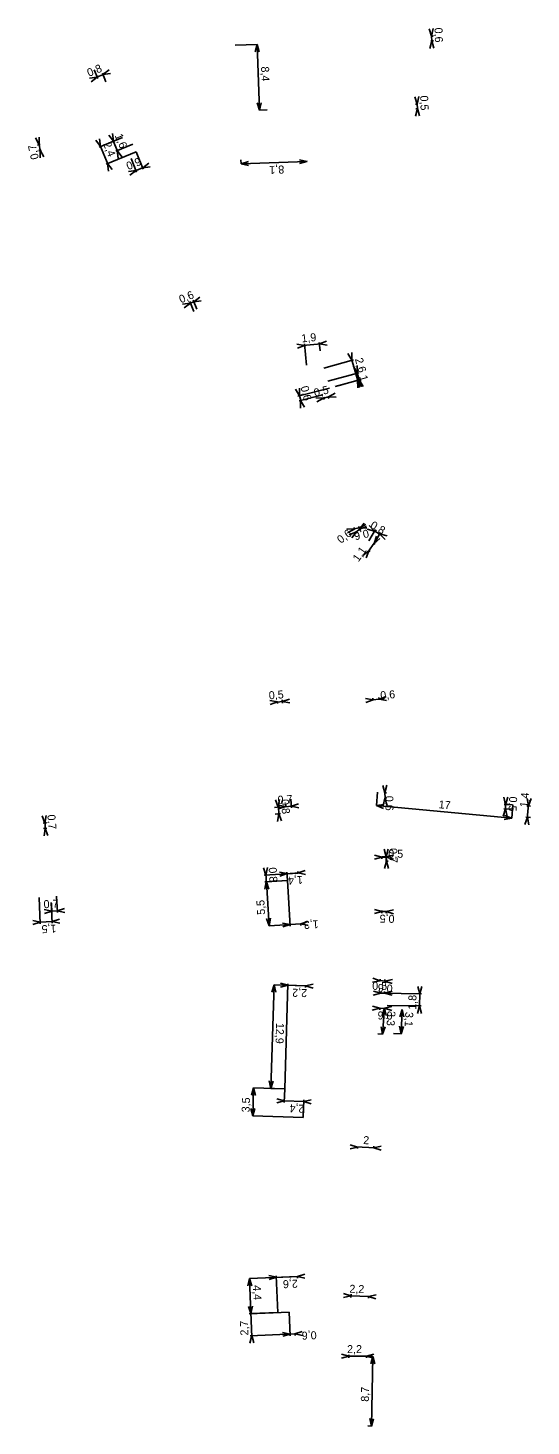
# Model space of a CAD drawing. Extents: x -732085 to -731961, y -1048713 to -1047966.
# Drawn here: x -732023.7 to -731960.7, y -1048713.1 to -1048538.4 of the extents above; entities that cross this region are included whole.
import ezdxf

# ---------------------------------------------------------------- set-up
doc = ezdxf.new("R2010")
doc.units = 0
doc.layers.add('Kota_NN', color=7, linetype='Continuous')
doc.layers.add('Kota_VN', color=7, linetype='Continuous')

msp = doc.modelspace()

# ---------------------------------------------------------------- linework, layer by layer
at = {"layer": 'Kota_NN'}
for p, q in [((-731973.19, -1048539.41), (-731973.47, -1048538.49)), ((-731973.19, -1048539.41), (-731972.97, -1048538.47)), ((-731997.73, -1048540.53), (-731995.01, -1048540.43)), ((-731995.01, -1048540.43), (-731995.23, -1048541.37)), ((-731995.01, -1048540.43), (-731994.7, -1048548.67)), ((-731995.01, -1048540.43), (-731994.73, -1048541.35)), ((-731973.16, -1048539.99), (-731973.38, -1048540.93)), ((-731973.27, -1048540), (-731972.96, -1048539.99)), ((-731973.26, -1048539.41), (-731972.98, -1048539.4)), ((-731973.19, -1048539.21), (-731973.16, -1048540.19)), ((-731973.16, -1048539.99), (-731972.88, -1048540.91)), ((-732015.38, -1048543.6), (-732014.93, -1048544.7)), ((-732015.19, -1048544.59), (-732014.09, -1048544.14)), ((-732013.9, -1048545.12), (-732014.35, -1048544.03)), ((-732014.28, -1048544.21), (-732013.51, -1048543.63)), ((-732014.28, -1048544.21), (-732013.33, -1048544.09)), ((-732015.01, -1048544.52), (-732015.96, -1048544.64)), ((-732015.01, -1048544.52), (-732015.77, -1048545.1)), ((-731974.98, -1048547.9), (-731975.26, -1048546.98)), ((-731974.98, -1048547.9), (-731974.76, -1048546.96)), ((-731974.98, -1048547.7), (-731974.95, -1048548.67)), ((-731994.7, -1048548.67), (-731994.99, -1048547.75)), ((-731994.7, -1048548.67), (-731994.49, -1048547.73)), ((-731993.73, -1048548.63), (-731994.7, -1048548.67)), ((-731974.95, -1048547.89), (-731975.18, -1048547.9)), ((-731974.96, -1048548.46), (-731975.18, -1048549.4)), ((-731974.95, -1048548.46), (-731975.16, -1048548.47)), ((-731974.96, -1048548.46), (-731974.68, -1048549.38)), ((-732022.27, -1048552.97), (-732022.72, -1048552.13)), ((-732022.14, -1048552.94), (-732022.46, -1048553.02)), ((-732022.07, -1048553.84), (-732022.31, -1048552.78)), ((-732022.27, -1048552.97), (-732022.24, -1048552.01)), ((-732014.58, -1048553.18), (-732015.16, -1048552.42)), ((-732011.84, -1048552.06), (-732014.76, -1048553.26)), ((-732014.58, -1048553.18), (-732014.7, -1048552.23)), ((-732012.97, -1048552.52), (-732013.55, -1048551.76)), ((-732011.84, -1048552.06), (-732013.16, -1048552.6)), ((-732012.97, -1048552.52), (-732013.09, -1048551.57)), ((-732013.05, -1048552.34), (-732012.41, -1048553.89)), ((-732010.53, -1048552.9), (-732012.67, -1048553.78)), ((-732021.99, -1048553.61), (-732022.31, -1048553.69)), ((-732022.11, -1048553.64), (-732022.14, -1048554.6)), ((-732022.11, -1048553.64), (-732021.66, -1048554.49)), ((-732014.65, -1048553), (-732013.63, -1048555.49)), ((-732010.14, -1048553.84), (-732013.89, -1048555.38)), ((-732012.48, -1048553.71), (-732011.9, -1048554.47)), ((-732012.48, -1048553.71), (-732012.36, -1048554.66)), ((-732010.14, -1048553.84), (-732009.24, -1048556.04)), ((-732013.71, -1048555.3), (-732013.13, -1048556.07)), ((-732013.71, -1048555.3), (-732013.59, -1048556.26)), ((-732010.14, -1048556.19), (-732011.1, -1048556.32)), ((-732010.14, -1048556.19), (-732010.91, -1048556.78)), ((-732010.75, -1048554.71), (-732010.07, -1048556.38)), ((-732010.33, -1048556.27), (-732009.13, -1048555.78)), ((-732009.31, -1048555.85), (-732008.55, -1048555.27)), ((-732009.31, -1048555.85), (-732008.36, -1048555.73)), ((-731997.02, -1048554.85), (-731997, -1048555.37)), ((-731988.77, -1048555.05), (-731997, -1048555.37)), ((-731997, -1048555.37), (-731996.08, -1048555.08)), ((-731997, -1048555.37), (-731996.06, -1048555.58)), ((-731988.77, -1048555.05), (-731989.71, -1048554.84)), ((-731988.77, -1048555.05), (-731989.69, -1048555.33)), ((-731988.77, -1048555), (-731988.77, -1048555.05)), ((-732002.93, -1048572.58), (-732002.17, -1048572)), ((-732003.35, -1048572.75), (-732004.31, -1048572.87)), ((-732003.35, -1048572.75), (-732004.12, -1048573.33)), ((-732003.54, -1048572.83), (-732002.75, -1048572.5)), ((-732002.93, -1048573.79), (-732003.43, -1048572.57)), ((-732002.55, -1048573.51), (-732003.01, -1048572.39)), ((-732002.93, -1048572.58), (-732001.98, -1048572.46)), ((-731989.07, -1048578.05), (-731990.02, -1048577.89)), ((-731989.07, -1048578.05), (-731989.97, -1048578.39)), ((-731989.27, -1048578.07), (-731987, -1048577.84)), ((-731988.82, -1048580.53), (-731989.09, -1048577.85)), ((-731987.12, -1048578.7), (-731987.22, -1048577.66)), ((-731987.2, -1048577.86), (-731986.31, -1048577.51)), ((-731987.2, -1048577.86), (-731986.25, -1048578.01)), ((-731982.46, -1048581.5), (-731982.95, -1048580.67)), ((-731982.46, -1048581.5), (-731982.47, -1048580.54)), ((-731986.16, -1048582.52), (-731982.27, -1048581.45)), ((-731985.22, -1048583.16), (-731982.04, -1048582.29)), ((-731982.51, -1048581.31), (-731982.18, -1048582.53)), ((-731982.23, -1048582.34), (-731981.75, -1048583.17)), ((-731982.23, -1048582.34), (-731982.22, -1048583.3)), ((-731986.09, -1048584.47), (-731985.25, -1048584.01)), ((-731986.68, -1048584.62), (-731987.64, -1048584.6)), ((-731986.68, -1048584.62), (-731987.52, -1048585.08)), ((-731986.87, -1048584.67), (-731985.9, -1048584.43)), ((-731986.71, -1048584.5), (-731986.63, -1048584.81)), ((-731986.11, -1048584.4), (-731986.05, -1048584.67)), ((-731986.09, -1048584.47), (-731985.13, -1048584.49)), ((-731982.58, -1048601.32), (-731983.47, -1048601.69)), ((-731982.58, -1048601.32), (-731983.17, -1048602.08)), ((-731982.74, -1048601.44), (-731982.03, -1048600.89)), ((-731982.65, -1048601.24), (-731982.46, -1048601.48)), ((-731982.22, -1048600.97), (-731982.06, -1048601.17)), ((-731982.19, -1048601.01), (-731981.6, -1048600.25)), ((-731982.19, -1048601.01), (-731981.3, -1048600.65)), ((-731980.31, -1048601.23), (-731981.24, -1048600.98)), ((-731981.01, -1048602.44), (-731980.21, -1048601.06)), ((-731980.31, -1048601.23), (-731980.99, -1048600.55)), ((-731980.48, -1048601.13), (-731979.51, -1048601.7)), ((-731980.37, -1048602.79), (-731979.58, -1048601.43)), ((-731979.68, -1048601.6), (-731978.75, -1048601.85)), ((-731979.68, -1048601.6), (-731979, -1048602.28)), ((-731981.15, -1048603.86), (-731980.27, -1048602.61)), ((-731980.4, -1048602.76), (-731980.22, -1048602.89)), ((-731980.38, -1048602.78), (-731980.05, -1048601.88)), ((-731980.38, -1048602.78), (-731979.64, -1048602.16)), ((-731981.03, -1048603.7), (-731981.77, -1048604.31)), ((-731981.03, -1048603.7), (-731981.36, -1048604.6)), ((-731981.09, -1048603.65), (-731980.87, -1048603.81)), ((-731992.45, -1048622.59), (-731993.39, -1048622.41)), ((-731992.45, -1048622.59), (-731993.35, -1048622.91)), ((-731992.65, -1048622.6), (-731991.65, -1048622.52)), ((-731992.45, -1048622.57), (-731992.43, -1048622.79)), ((-731991.87, -1048622.33), (-731991.84, -1048622.74)), ((-731991.85, -1048622.54), (-731990.95, -1048622.22)), ((-731991.85, -1048622.54), (-731990.91, -1048622.71)), ((-731980.49, -1048622.31), (-731981.44, -1048622.15)), ((-731980.49, -1048622.31), (-731981.39, -1048622.64)), ((-731980.69, -1048622.33), (-731979.55, -1048622.23)), ((-731980.49, -1048622.34), (-731980.51, -1048622.11)), ((-731979.75, -1048622.27), (-731979.77, -1048622.05)), ((-731979.75, -1048622.25), (-731978.85, -1048621.92)), ((-731979.75, -1048622.25), (-731978.81, -1048622.41)), ((-731979.02, -1048633.93), (-731979.28, -1048633.01)), ((-731979.02, -1048633.93), (-731978.79, -1048633)), ((-731992.36, -1048635.72), (-731992.7, -1048634.82)), ((-731992.36, -1048635.72), (-731992.2, -1048634.77)), ((-731990.77, -1048634.74), (-731990.71, -1048635.82)), ((-731979.93, -1048633.86), (-731980.09, -1048635.54)), ((-731979.01, -1048634.59), (-731979.24, -1048635.52)), ((-731979.04, -1048633.93), (-731978.82, -1048633.93)), ((-731979.04, -1048634.59), (-731978.81, -1048634.59)), ((-731979.02, -1048633.73), (-731979, -1048634.79)), ((-731979.01, -1048634.59), (-731978.74, -1048635.52)), ((-731963.92, -1048635.42), (-731964.13, -1048634.48)), ((-731963.92, -1048635.42), (-731963.63, -1048634.5)), ((-731961.07, -1048635.57), (-731961.24, -1048634.63)), ((-731961.07, -1048635.57), (-731960.74, -1048634.67)), ((-732021.55, -1048637.72), (-732021.38, -1048636.77)), ((-731992.82, -1048635.77), (-731992.16, -1048635.7)), ((-731992.73, -1048636.61), (-731992.08, -1048636.54)), ((-731992.27, -1048636.56), (-731992.43, -1048637.51)), ((-731992.38, -1048635.52), (-731992.25, -1048636.76)), ((-731991.41, -1048635.66), (-731992.35, -1048635.47)), ((-731991.41, -1048635.66), (-731992.32, -1048635.96)), ((-731992.27, -1048636.56), (-731991.94, -1048637.46)), ((-731991.61, -1048635.67), (-731990.52, -1048635.61)), ((-731991.41, -1048635.67), (-731991.42, -1048635.46)), ((-731990.72, -1048635.62), (-731989.81, -1048635.32)), ((-731990.72, -1048635.62), (-731989.78, -1048635.81)), ((-731980.09, -1048635.54), (-731979.14, -1048635.38)), ((-731980.09, -1048635.54), (-731963.16, -1048637.12)), ((-731980.09, -1048635.54), (-731979.19, -1048635.88)), ((-731963.95, -1048635.96), (-731964.25, -1048636.87)), ((-731963.1, -1048636), (-731964.15, -1048635.95)), ((-731963.07, -1048635.46), (-731964.12, -1048635.41)), ((-731963.16, -1048637.12), (-731964.06, -1048636.78)), ((-731963.91, -1048635.22), (-731963.96, -1048636.16)), ((-731963.95, -1048635.96), (-731963.75, -1048636.89)), ((-731963.01, -1048635.43), (-731963.16, -1048637.12)), ((-731960.8, -1048635.6), (-731961.27, -1048635.55)), ((-731961.22, -1048637.19), (-731961.06, -1048635.37)), ((-732021.55, -1048637.72), (-732021.88, -1048636.82)), ((-732021.76, -1048637.74), (-732021.35, -1048637.7)), ((-732021.7, -1048638.4), (-732021.29, -1048638.37)), ((-732021.49, -1048638.39), (-732021.65, -1048639.33)), ((-732021.56, -1048637.52), (-732021.47, -1048638.58)), ((-732021.49, -1048638.39), (-732021.16, -1048639.29)), ((-731963.16, -1048637.12), (-731964.11, -1048637.28)), ((-731961.2, -1048636.99), (-731961.54, -1048637.89)), ((-731960.83, -1048637.02), (-731961.4, -1048636.97)), ((-731961.2, -1048636.99), (-731961.04, -1048637.93)), ((-731979.39, -1048641.97), (-731980.32, -1048641.71)), ((-731979.39, -1048641.97), (-731980.32, -1048642.21)), ((-731979.59, -1048641.96), (-731978.66, -1048641.97)), ((-731979.39, -1048641.94), (-731978.65, -1048641.92)), ((-731979.39, -1048641.94), (-731979.39, -1048642.17)), ((-731978.85, -1048641.92), (-731979.12, -1048641)), ((-731978.86, -1048641.97), (-731977.93, -1048641.72)), ((-731978.86, -1048642.47), (-731978.86, -1048641.77)), ((-731978.86, -1048641.97), (-731977.94, -1048642.22)), ((-731978.85, -1048641.92), (-731978.62, -1048640.99)), ((-731978.85, -1048641.72), (-731978.83, -1048642.67)), ((-731993.91, -1048644.21), (-731994.21, -1048643.3)), ((-731993.91, -1048644.21), (-731993.71, -1048643.27)), ((-731989.88, -1048643.96), (-731989.89, -1048643.75)), ((-731989.88, -1048643.95), (-731988.97, -1048643.64)), ((-731978.83, -1048642.47), (-731979.05, -1048643.4)), ((-731978.86, -1048642.47), (-731978.63, -1048642.46)), ((-731978.83, -1048642.47), (-731978.56, -1048643.39)), ((-731989.88, -1048643.96), (-731994.1, -1048644.22)), ((-731991.2, -1048644.89), (-731994.05, -1048645.07)), ((-731993.85, -1048645.05), (-731994.04, -1048645.99)), ((-731993.84, -1048645.05), (-731994.04, -1048645.99)), ((-731993.92, -1048644.01), (-731993.84, -1048645.25)), ((-731993.85, -1048645.05), (-731993.55, -1048645.96)), ((-731991.2, -1048644.89), (-731993.84, -1048645.05)), ((-731993.51, -1048650.55), (-731993.84, -1048645.05)), ((-731993.84, -1048645.05), (-731993.54, -1048645.96)), ((-731991.25, -1048644.04), (-731992.2, -1048643.85)), ((-731991.25, -1048644.04), (-731992.16, -1048644.34)), ((-731989.68, -1048643.94), (-731991.45, -1048644.05)), ((-731991.2, -1048644.89), (-731991.27, -1048643.84)), ((-731991.2, -1048644.89), (-731990.85, -1048650.6)), ((-731989.88, -1048643.95), (-731988.94, -1048644.14)), ((-732022.27, -1048647.01), (-732022.11, -1048650.29)), ((-732020.07, -1048646.85), (-732019.98, -1048648.88)), ((-732020.69, -1048648.72), (-732021.62, -1048648.51)), ((-732020.69, -1048648.72), (-732021.6, -1048649.01)), ((-732020.89, -1048648.73), (-732019.79, -1048648.68)), ((-732020.74, -1048647.64), (-732020.62, -1048650.23)), ((-732020.73, -1048647.73), (-732020.68, -1048648.92)), ((-732019.99, -1048648.68), (-732019.07, -1048648.39)), ((-732019.99, -1048648.68), (-732019.05, -1048648.89)), ((-731979.39, -1048648.76), (-731980.32, -1048649)), ((-731979.39, -1048648.76), (-731980.31, -1048648.5)), ((-731978.67, -1048648.77), (-731979.59, -1048648.76)), ((-731979.39, -1048648.66), (-731979.39, -1048648.96)), ((-731978.87, -1048648.72), (-731978.88, -1048648.97)), ((-731978.87, -1048648.77), (-731977.94, -1048648.54)), ((-731978.87, -1048648.77), (-731977.95, -1048649.04)), ((-732022.12, -1048650.09), (-732023.06, -1048649.89)), ((-732022.12, -1048650.09), (-732023.04, -1048650.38)), ((-732020.43, -1048650.02), (-732022.32, -1048650.1)), ((-732020.63, -1048650.02), (-732019.71, -1048649.73)), ((-732020.63, -1048650.02), (-732019.69, -1048650.23)), ((-731993.51, -1048650.55), (-731993.81, -1048649.64)), ((-731993.51, -1048650.55), (-731993.31, -1048649.61)), ((-731989.55, -1048650.31), (-731993.51, -1048650.55)), ((-731990.86, -1048650.4), (-731991.81, -1048650.21)), ((-731990.86, -1048650.4), (-731991.78, -1048650.7)), ((-731989.35, -1048650.31), (-731991.06, -1048650.41)), ((-731989.55, -1048650.32), (-731988.64, -1048650.02)), ((-731989.55, -1048650.31), (-731989.54, -1048650.52)), ((-731989.55, -1048650.32), (-731988.61, -1048650.51)), ((-731991.16, -1048657.99), (-731992.08, -1048657.71)), ((-731992.88, -1048657.93), (-731993.27, -1048670.87)), ((-731992.88, -1048657.93), (-731993.15, -1048658.85)), ((-731988.93, -1048658.05), (-731992.88, -1048657.93)), ((-731992.88, -1048657.93), (-731992.66, -1048658.86)), ((-731991.16, -1048657.99), (-731992.09, -1048658.21)), ((-731991.55, -1048670.92), (-731991.15, -1048657.79)), ((-731988.73, -1048658.07), (-731991.36, -1048657.99)), ((-731988.93, -1048658.05), (-731988.94, -1048658.26)), ((-731988.93, -1048658.06), (-731987.99, -1048657.84)), ((-731988.93, -1048658.06), (-731988.01, -1048658.34)), ((-731979.54, -1048658.97), (-731980.47, -1048659.2)), ((-731979.54, -1048658.97), (-731980.46, -1048658.7)), ((-731979.74, -1048658.97), (-731978.85, -1048658.98)), ((-731979.54, -1048658.98), (-731979.54, -1048658.77)), ((-731979.54, -1048658.98), (-731974.46, -1048659.07)), ((-731979.05, -1048658.98), (-731978.12, -1048658.74)), ((-731979.05, -1048659.01), (-731979.05, -1048658.78)), ((-731979.05, -1048658.98), (-731978.12, -1048659.24)), ((-731974.66, -1048659.06), (-731974.89, -1048658.13)), ((-731974.69, -1048660.77), (-731974.66, -1048658.86)), ((-731974.66, -1048659.06), (-731974.4, -1048658.14)), ((-731979.67, -1048660.85), (-731980.6, -1048661.09)), ((-731979.67, -1048660.85), (-731980.59, -1048660.59)), ((-731978.89, -1048660.87), (-731979.87, -1048660.85)), ((-731979.67, -1048660.85), (-731979.67, -1048661.05)), ((-731979.06, -1048660.83), (-731979.37, -1048661.74)), ((-731979.06, -1048660.83), (-731979.3, -1048664.1)), ((-731979.09, -1048660.86), (-731978.16, -1048660.63)), ((-731979.09, -1048660.83), (-731979.09, -1048661.06)), ((-731979.09, -1048660.86), (-731978.16, -1048661.13)), ((-731979.08, -1048660.83), (-731979.06, -1048660.83)), ((-731979.06, -1048660.83), (-731978.88, -1048661.77)), ((-731978.72, -1048660.5), (-731974.49, -1048660.57)), ((-731974.69, -1048660.57), (-731974.95, -1048661.49)), ((-731974.69, -1048660.57), (-731974.46, -1048661.5)), ((-731979.92, -1048664.06), (-731979.3, -1048664.1)), ((-731979.3, -1048664.1), (-731979.48, -1048663.16)), ((-731979.3, -1048664.1), (-731978.98, -1048663.19)), ((-731993.27, -1048670.87), (-731993.49, -1048669.93)), ((-731993.27, -1048670.87), (-731993, -1048669.95)), ((-731995.44, -1048670.8), (-731995.72, -1048671.72)), ((-731995.55, -1048674.3), (-731995.44, -1048670.8)), ((-731991.55, -1048670.92), (-731995.44, -1048670.8)), ((-731995.44, -1048670.8), (-731995.22, -1048671.74)), ((-731991.55, -1048670.92), (-731993.27, -1048670.87)), ((-731991.55, -1048670.92), (-731991.6, -1048672.64)), ((-731995.55, -1048674.3), (-731995.77, -1048673.37)), ((-731995.55, -1048674.3), (-731995.27, -1048673.39)), ((-731991.6, -1048672.44), (-731992.53, -1048672.66)), ((-731991.6, -1048672.44), (-731992.52, -1048672.16)), ((-731988.97, -1048672.52), (-731991.8, -1048672.43)), ((-731989.23, -1048674.5), (-731989.16, -1048672.31)), ((-731989.17, -1048672.51), (-731988.23, -1048672.29)), ((-731989.17, -1048672.51), (-731988.25, -1048672.79)), ((-731989.23, -1048674.5), (-731995.55, -1048674.3)), ((-731982.44, -1048678.19), (-731983.38, -1048678.4)), ((-731982.44, -1048678.19), (-731983.36, -1048677.9)), ((-731982.64, -1048678.18), (-731980.22, -1048678.29)), ((-731982.44, -1048678.17), (-731982.45, -1048678.39)), ((-731980.42, -1048678.29), (-731979.48, -1048678.08)), ((-731980.42, -1048678.3), (-731980.41, -1048678.09)), ((-731980.42, -1048678.29), (-731979.5, -1048678.58)), ((-731989.96, -1048694.35), (-731995.95, -1048694.6)), ((-731992.59, -1048694.47), (-731993.53, -1048694.26)), ((-731989.76, -1048694.35), (-731992.79, -1048694.48)), ((-731992.41, -1048698.87), (-731992.6, -1048694.27)), ((-731989.96, -1048694.36), (-731989.04, -1048694.07)), ((-731989.96, -1048694.35), (-731989.95, -1048694.56)), ((-731989.96, -1048694.36), (-731989.02, -1048694.57)), ((-731995.95, -1048694.6), (-731996.16, -1048695.54)), ((-731995.95, -1048694.6), (-731995.77, -1048699.01)), ((-731995.95, -1048694.6), (-731995.67, -1048695.52)), ((-731992.59, -1048694.47), (-731993.51, -1048694.76)), ((-731983.26, -1048696.79), (-731984.19, -1048697.01)), ((-731983.26, -1048696.79), (-731984.18, -1048696.51)), ((-731983.46, -1048696.79), (-731980.85, -1048696.87)), ((-731983.25, -1048696.59), (-731983.27, -1048696.99)), ((-731981.06, -1048696.87), (-731980.12, -1048696.65)), ((-731981.05, -1048696.79), (-731981.06, -1048697.07)), ((-731981.06, -1048696.87), (-731980.14, -1048697.15)), ((-731995.8, -1048699.01), (-731996.08, -1048698.1)), ((-731995.77, -1048699.01), (-731996.06, -1048698.1)), ((-731990.99, -1048698.81), (-731995.99, -1048699.02)), ((-731995.8, -1048699.01), (-731995.59, -1048698.08)), ((-731995.67, -1048701.95), (-731995.8, -1048698.81)), ((-731995.77, -1048699.01), (-731995.56, -1048698.07)), ((-731992.41, -1048698.87), (-731995.77, -1048699.01)), ((-731990.99, -1048698.81), (-731990.86, -1048701.76)), ((-731990.87, -1048701.56), (-731991.81, -1048701.35)), ((-731990.27, -1048701.53), (-731989.35, -1048701.24)), ((-731995.68, -1048701.75), (-731995.89, -1048702.69)), ((-731990.27, -1048701.52), (-731995.88, -1048701.76)), ((-731995.68, -1048701.75), (-731995.39, -1048702.67)), ((-731990.87, -1048701.56), (-731991.79, -1048701.84)), ((-731990.07, -1048701.52), (-731991.07, -1048701.56)), ((-731990.27, -1048701.52), (-731990.26, -1048701.73)), ((-731990.27, -1048701.53), (-731989.33, -1048701.74)), ((-731983.51, -1048704.34), (-731984.43, -1048704.09)), ((-731983.51, -1048704.34), (-731984.43, -1048704.59)), ((-731983.7, -1048704.34), (-731981.14, -1048704.34)), ((-731983.51, -1048704.17), (-731983.51, -1048704.54)), ((-731981.33, -1048704.34), (-731980.41, -1048704.09)), ((-731981.33, -1048704.33), (-731981.33, -1048704.54)), ((-731981.33, -1048704.33), (-731980.51, -1048704.35)), ((-731981.33, -1048704.34), (-731980.41, -1048704.59)), ((-731980.51, -1048704.35), (-731980.78, -1048705.27)), ((-731980.7, -1048713.05), (-731980.51, -1048704.35)), ((-731980.51, -1048704.35), (-731980.28, -1048705.28)), ((-731981.17, -1048713.04), (-731980.7, -1048713.05)), ((-731980.7, -1048713.05), (-731980.92, -1048712.12)), ((-731980.7, -1048713.05), (-731980.43, -1048712.13))]:
    msp.add_line(p, q, dxfattribs=at)
at = {"layer": 'Kota_VN'}
for p, q in [((-731983.15, -1048579.89), (-731983.65, -1048579.06)), ((-731983.15, -1048579.89), (-731983.17, -1048578.93)), ((-731986.66, -1048580.9), (-731982.96, -1048579.83)), ((-731983.21, -1048579.7), (-731982.38, -1048582.58)), ((-731984.88, -1048583.09), (-731982.24, -1048582.33)), ((-731982.43, -1048582.39), (-731981.94, -1048583.21)), ((-731982.43, -1048582.39), (-731982.42, -1048583.35)), ((-731989.71, -1048584.33), (-731990.18, -1048583.49)), ((-731985.95, -1048583.38), (-731989.9, -1048584.38)), ((-731989.76, -1048584.13), (-731989.51, -1048585.11)), ((-731986.77, -1048584.22), (-731989.75, -1048584.97)), ((-731989.71, -1048584.33), (-731989.69, -1048583.37)), ((-731989.56, -1048584.92), (-731989.57, -1048585.88)), ((-731989.56, -1048584.92), (-731989.09, -1048585.76)), ((-731982.82, -1048600.98), (-731983.78, -1048600.94)), ((-731982.82, -1048600.98), (-731983.67, -1048601.42)), ((-731982.06, -1048600.81), (-731983.01, -1048601.02)), ((-731982.82, -1048600.99), (-731982.86, -1048600.78)), ((-731982.25, -1048600.86), (-731982.3, -1048600.66)), ((-731982.25, -1048600.85), (-731981.4, -1048600.4)), ((-731982.25, -1048600.85), (-731981.29, -1048600.89)), ((-731979.61, -1048657.42), (-731980.55, -1048657.6)), ((-731979.61, -1048657.42), (-731980.52, -1048657.11)), ((-731978.83, -1048657.47), (-731979.81, -1048657.4)), ((-731979.61, -1048657.43), (-731979.6, -1048657.22)), ((-731979.03, -1048657.46), (-731979.02, -1048657.25)), ((-731979.03, -1048657.45), (-731978.09, -1048657.26)), ((-731979.03, -1048657.45), (-731978.12, -1048657.76)), ((-731976.85, -1048660.99), (-731977.14, -1048661.91)), ((-731976.85, -1048660.99), (-731977, -1048664.04)), ((-731976.84, -1048660.99), (-731976.85, -1048660.99)), ((-731976.85, -1048660.99), (-731976.65, -1048661.93)), ((-731977.95, -1048663.99), (-731977, -1048664.04)), ((-731977, -1048664.04), (-731977.2, -1048663.1)), ((-731977, -1048664.04), (-731976.71, -1048663.12))]:
    msp.add_line(p, q, dxfattribs=at)

# ---------------------------------------------------------------- texts
at = {"layer": 'Kota_NN'}
for s, rotation, p in [('0,6', 272.154, (-731972.82, -1048538.36)), ('0,8', 22.3966, (-732016.02, -1048544.5)), ('8,4', 272.1541, (-731994.51, -1048543.21)), ('0,5', 271.838, (-731974.61, -1048546.84)), ('2,4', 292.3009, (-732014.28, -1048552.86)), ('1,6', 292.3011, (-732012.83, -1048551.82)), ('0,7', 103.1492, (-732022.28, -1048554.69)), ('0,9', 22.301, (-732011.11, -1048556.16)), ('8,1', 182.2066, (-731991.63, -1048555.56)), ('0,6', 22.3009, (-732004.52, -1048572.8)), ('1,9', 5.8362, (-731989.41, -1048577.68)), ('1', 285.3592, (-731982.23, -1048581.91)), ('0,5', 13.8482, (-731987.77, -1048584.47)), ('0,8', 329.8384, (-731980.95, -1048600.78)), ('0,6', 37.6234, (-731984.53, -1048602.85)), ('1,1', 54.7115, (-731982.33, -1048605.16)), ('0,5', 4.553, (-731993.5, -1048622.27)), ('0,6', 5.1049, (-731979.55, -1048622.27)), ('0,7', 3.3665, (-731992.41, -1048635.32)), ('0,8', 275.682, (-731992.05, -1048634.78)), ('0,6', 271.0912, (-731978.97, -1048634.32)), ('17', 354.6874, (-731972.33, -1048635.86)), ('0,5', 267.1429, (-731963.47, -1048634.38)), ('1,4', 84.7507, (-731961.16, -1048635.8)), ('0,7', 275.1239, (-732021.24, -1048636.7)), ('0,7', 271.6576, (-731978.48, -1048640.86)), ('0,5', 359.746, (-731978.6, -1048642.05)), ('0,8', 273.5214, (-731993.56, -1048643.28)), ('1,4', 183.6152, (-731989.3, -1048644.31)), ('0,7', 2.6428, (-732021.68, -1048648.36)), ('5,5', 93.5215, (-731993.99, -1048649.15)), ('0,5', 179.0363, (-731977.81, -1048649.19)), ('1,5', 182.6424, (-732020.12, -1048650.4)), ('1,3', 183.4909, (-731987.33, -1048649.85)), ('0,5', 359.0364, (-731980.61, -1048658.55)), ('2,2', 178.2529, (-731988.73, -1048658.47)), ('1,8', 89.034, (-731975.1, -1048661.05)), ('0,6', 179.0384, (-731978.06, -1048661.28)), ('3,3', 265.8961, (-731978.68, -1048661.17)), ('12,9', 268.2373, (-731992.62, -1048662.67)), ('3,5', 88.2376, (-731995.94, -1048673.87)), ('2,4', 178.2254, (-731989.07, -1048672.92)), ('2', 357.3836, (-731981.75, -1048677.82)), ('4,4', 272.4194, (-731995.52, -1048695.47)), ('2,6', 182.3704, (-731989.93, -1048694.76)), ('2,2', 358.087, (-731983.47, -1048696.39)), ('2,7', 92.4194, (-731996.08, -1048701.72)), ('0,6', 182.495, (-731987.58, -1048701.19)), ('8,7', 88.764, (-731981.03, -1048710.02))]:
    msp.add_text(s, height=1, rotation=rotation, dxfattribs=at).set_placement(p)
msp.add_text('2,2', height=1, dxfattribs=at).set_placement((-731983.75, -1048703.94))
at = {"layer": 'Kota_VN'}
for s, rotation, p in [('2,6', 286.06, (-731982.78, -1048579.75)), ('0,6', 284.1303, (-731989.57, -1048583.24)), ('0,6', 192.7047, (-731981.15, -1048601.01)), ('0,6', 176.3848, (-731978.02, -1048657.92)), ('3,1', 267.1313, (-731976.46, -1048661.29))]:
    msp.add_text(s, height=1, rotation=rotation, dxfattribs=at).set_placement(p)

doc.saveas('drawing.dxf')
